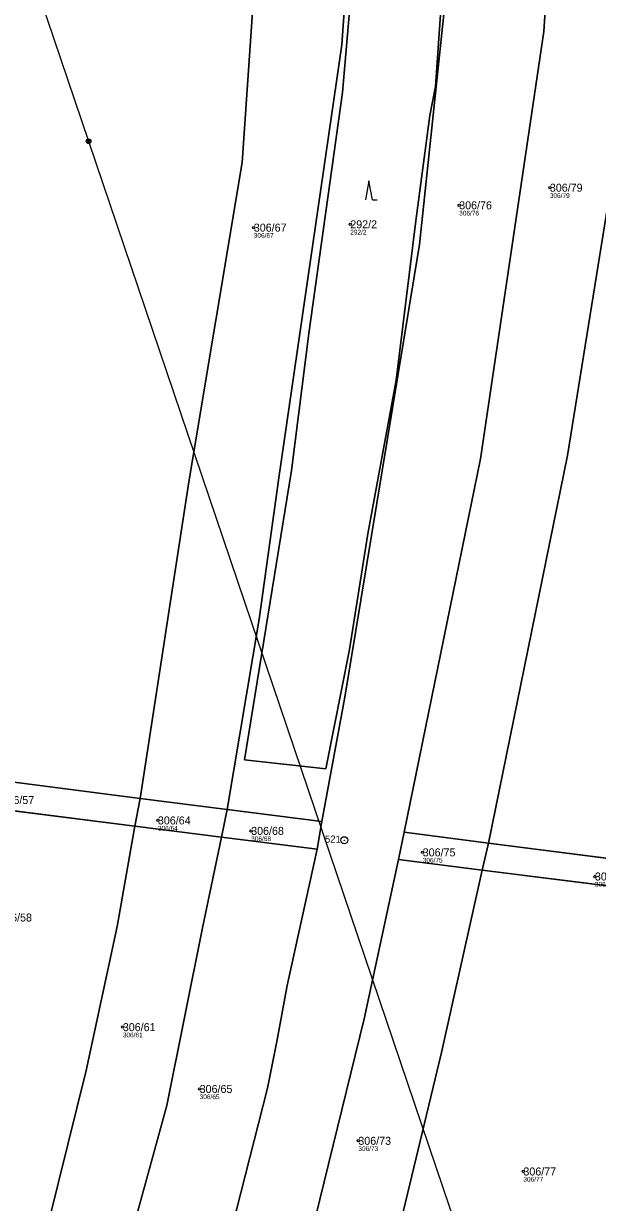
# Model space of a CAD drawing. Extents: x -732749 to -730903, y -1025757 to -1023435.
# Drawn here: x -732153.5 to -732031.6, y -1024046.3 to -1023795.9 of the extents above; entities that cross this region are included whole.
import ezdxf

# ---------------------------------------------------------------- set-up
doc = ezdxf.new("R2010")
doc.units = 0
for name, color, linetype in [('Definiční body', 7, 'Continuous'), ('Hranice parcel', 7, 'Continuous'), ('Parcelní čísla', 7, 'Continuous'), ('Polygon parcely', 7, 'Continuous'), ('Poz předměty', 7, 'Continuous'), ('Značky bodu BP', 7, 'Continuous'), ('Značky kultur', 7, 'Continuous')]:
    doc.layers.add(name, color=color, linetype=linetype)

msp = doc.modelspace()

# ---------------------------------------------------------------- linework, layer by layer
at = {"layer": 'Definiční body'}
for centre in [(-732041.74, -1023830.79), (-732061, -1023834.53), (-732084.13, -1023838.57), (-732104.62, -1023839.27), (-732124.99, -1023965.19), (-732105.18, -1023967.41), (-732068.74, -1023971.98), (-732032.17, -1023977.1), (-732132.44, -1024009.1), (-732116.12, -1024022.23), (-732082.42, -1024033.24), (-732047.36, -1024039.76)]:
    msp.add_circle(centre, 0.25, dxfattribs=at)
at = {"layer": 'Hranice parcel'}
for p, q in [((-732128.74, -1023960.5), (-732179.66, -1023953.96)), ((-732180.5, -1023959.99), (-732129.9, -1023966.39)), ((-732129.9, -1023966.39), (-732128.74, -1023960.5)), ((-732110.27, -1023962.87), (-732128.74, -1023960.5)), ((-732111.48, -1023968.72), (-732110.27, -1023962.87)), ((-732090.15, -1023965.45), (-732110.27, -1023962.87)), ((-732111.48, -1023968.72), (-732129.9, -1023966.39)), ((-732091.17, -1023971.29), (-732090.15, -1023965.45)), ((-732091.17, -1023971.29), (-732111.48, -1023968.72)), ((-732072.66, -1023967.7), (-732073.86, -1023973.48)), ((-732054.8, -1023969.99), (-732072.66, -1023967.7)), ((-732056.09, -1023975.73), (-732054.8, -1023969.99)), ((-732054.8, -1023969.99), (-732003.11, -1023976.63)), ((-732056.09, -1023975.73), (-732073.86, -1023973.48)), ((-732003.09, -1023982.44), (-732056.09, -1023975.73))]:
    msp.add_line(p, q, dxfattribs=at)
for points in [[(-732036.08, -1023589.28), (-732022.93, -1023663.95), (-732019.55, -1023730.55), (-732024.06, -1023791.81), (-732027.06, -1023819.97), (-732038.02, -1023887.66), (-732054.8, -1023969.99)], [(-732072.66, -1023967.7), (-732056.45, -1023888.41), (-732042.99, -1023797.62), (-732039.38, -1023741.93), (-732043.18, -1023668.74), (-732056.15, -1023593.74)], [(-732128.74, -1023960.5), (-732118.32, -1023892.87), (-732107.12, -1023825.41), (-732104.19, -1023783.08), (-732102.37, -1023712.48), (-732104.44, -1023690.34), (-732112.29, -1023646.68), (-732119.93, -1023609.35)], [(-732110.27, -1023962.87), (-732103.47, -1023922.44), (-732099.33, -1023892.42), (-732085.94, -1023800.46), (-732084.11, -1023774.04), (-732083.75, -1023721.22), (-732084.36, -1023701.11), (-732086.06, -1023667.51), (-732086.71, -1023664.35)], [(-732062.59, -1023702.22), (-732077.45, -1023704.23), (-732082.56, -1023729.6), (-732081.88, -1023757.53), (-732083.67, -1023785.88), (-732085.75, -1023810.56), (-732092.92, -1023861.75), (-732096.63, -1023890.89), (-732106.63, -1023952.3), (-732089.32, -1023954.25), (-732084.32, -1023928.9), (-732080.38, -1023904.28), (-732074.4, -1023871.65), (-732070.21, -1023837.84), (-732067.22, -1023815.43), (-732066.05, -1023809.26), (-732064.06, -1023780.67), (-732062.95, -1023756.61)], [(-732090.15, -1023965.45), (-732085.27, -1023938.99), (-732069.44, -1023842.88), (-732063.59, -1023787.85), (-732060.67, -1023744.81), (-732061.84, -1023718.91)], [(-732151.95, -1024065.77), (-732140.23, -1024018.31), (-732133.67, -1023987.73), (-732129.9, -1023966.39)], [(-732139.79, -1024086.53), (-732123.1, -1024025.74), (-732115.5, -1023988.01), (-732111.48, -1023968.72)], [(-732124.31, -1024110.73), (-732101.74, -1024022.07), (-732099.68, -1024011.8), (-732097.5, -1024000.25), (-732091.17, -1023971.29)], [(-732073.86, -1023973.48), (-732081.19, -1024007.32), (-732095.31, -1024065.03), (-732111.61, -1024129.23)], [(-732097.33, -1024149.54), (-732080.94, -1024081.88), (-732064.77, -1024014.51), (-732056.09, -1023975.73)]]:
    msp.add_lwpolyline(points, dxfattribs=at)
at = {"layer": 'Polygon parcely'}
for points in [[(-732042.6, -1023590.79), (-732056.15, -1023593.74), (-732043.18, -1023668.74), (-732039.38, -1023741.93), (-732042.99, -1023797.62), (-732056.45, -1023888.41), (-732072.66, -1023967.7), (-732054.8, -1023969.99), (-732038.02, -1023887.66), (-732027.06, -1023819.97), (-732024.06, -1023791.81), (-732019.55, -1023730.55), (-732022.93, -1023663.95), (-732036.08, -1023589.28)], [(-732084.11, -1023774.04), (-732083.75, -1023721.22), (-732084.36, -1023701.11), (-732086.06, -1023667.51), (-732086.71, -1023664.35), (-732099.14, -1023604.25), (-732105.34, -1023605.84), (-732107.54, -1023606.6), (-732119.93, -1023609.35), (-732112.29, -1023646.68), (-732104.44, -1023690.34), (-732102.37, -1023712.48), (-732104.19, -1023783.08), (-732107.12, -1023825.41), (-732118.32, -1023892.87), (-732128.74, -1023960.5), (-732110.27, -1023962.87), (-732103.47, -1023922.44), (-732099.33, -1023892.42), (-732085.94, -1023800.46)], [(-732084.32, -1023928.9), (-732080.38, -1023904.28), (-732074.4, -1023871.65), (-732070.21, -1023837.84), (-732067.22, -1023815.43), (-732066.05, -1023809.26), (-732064.06, -1023780.67), (-732062.95, -1023756.61), (-732061.84, -1023718.91), (-732062.59, -1023702.22), (-732077.45, -1023704.23), (-732082.56, -1023729.6), (-732081.88, -1023757.53), (-732083.67, -1023785.88), (-732085.75, -1023810.56), (-732092.92, -1023861.75), (-732096.63, -1023890.89), (-732106.63, -1023952.3), (-732089.32, -1023954.25)], [(-732179.66, -1023953.96), (-732180.5, -1023959.99), (-732129.9, -1023966.39), (-732128.74, -1023960.5)], [(-732140.23, -1024018.31), (-732133.67, -1023987.73), (-732129.9, -1023966.39), (-732180.5, -1023959.99), (-732182.72, -1023981.88), (-732168.36, -1024033.68), (-732166.14, -1024041.84), (-732151.95, -1024065.77)], [(-732111.48, -1023968.72), (-732110.27, -1023962.87), (-732128.74, -1023960.5), (-732129.9, -1023966.39)], [(-732090.15, -1023965.45), (-732110.27, -1023962.87), (-732111.48, -1023968.72), (-732091.17, -1023971.29)], [(-732139.79, -1024086.53), (-732123.1, -1024025.74), (-732115.5, -1023988.01), (-732111.48, -1023968.72), (-732129.9, -1023966.39), (-732133.67, -1023987.73), (-732140.23, -1024018.31), (-732151.95, -1024065.77)], [(-732091.17, -1023971.29), (-732111.48, -1023968.72), (-732115.5, -1023988.01), (-732123.1, -1024025.74), (-732139.79, -1024086.53), (-732124.31, -1024110.73), (-732101.74, -1024022.07), (-732099.68, -1024011.8), (-732097.5, -1024000.25)], [(-732072.66, -1023967.7), (-732073.86, -1023973.48), (-732056.09, -1023975.73), (-732054.8, -1023969.99)], [(-732003.11, -1023976.63), (-732054.8, -1023969.99), (-732056.09, -1023975.73), (-732003.09, -1023982.44), (-732002.86, -1023981.47), (-732001.89, -1023976.79)], [(-732095.31, -1024065.03), (-732111.61, -1024129.23), (-732097.33, -1024149.54), (-732080.94, -1024081.88), (-732064.77, -1024014.51), (-732056.09, -1023975.73), (-732073.86, -1023973.48), (-732081.19, -1024007.32)], [(-732056.09, -1023975.73), (-732064.77, -1024014.51), (-732080.94, -1024081.88), (-732097.33, -1024149.54), (-732089.08, -1024157.41), (-732078.69, -1024168.01), (-732061.81, -1024177.45), (-732053.95, -1024182.72), (-732042.4, -1024181.79), (-732033.04, -1024124.93), (-732026.75, -1024089.8), (-732013.67, -1024026.69), (-732003.09, -1023982.44)]]:
    msp.add_lwpolyline(points, close=True, dxfattribs=at)
for points in [[(-732063.59, -1023787.85), (-732069.44, -1023842.88), (-732085.27, -1023938.99), (-732090.15, -1023965.45), (-732091.17, -1023971.29), (-732097.5, -1024000.25), (-732099.68, -1024011.8), (-732101.74, -1024022.07), (-732124.31, -1024110.73), (-732111.61, -1024129.23), (-732095.31, -1024065.03), (-732081.19, -1024007.32), (-732073.86, -1023973.48), (-732072.66, -1023967.7), (-732056.45, -1023888.41), (-732042.99, -1023797.62), (-732039.38, -1023741.93)], [(-732084.11, -1023774.04), (-732085.94, -1023800.46), (-732099.33, -1023892.42), (-732103.47, -1023922.44), (-732110.27, -1023962.87), (-732090.15, -1023965.45), (-732085.27, -1023938.99), (-732069.44, -1023842.88), (-732063.59, -1023787.85)], [(-732064.06, -1023780.67), (-732066.05, -1023809.26), (-732067.22, -1023815.43), (-732070.21, -1023837.84), (-732074.4, -1023871.65), (-732080.38, -1023904.28), (-732084.32, -1023928.9), (-732089.32, -1023954.25), (-732106.63, -1023952.3), (-732096.63, -1023890.89), (-732092.92, -1023861.75), (-732085.75, -1023810.56), (-732083.67, -1023785.88)], [(-732156.48, -1023792.71), (-732157.8, -1023805.88), (-732159.04, -1023823.95), (-732159.91, -1023832.93), (-732161.71, -1023842.63), (-732163.76, -1023854.8), (-732165.07, -1023863.63), (-732166.25, -1023868.78), (-732169.72, -1023885.73), (-732171.34, -1023897.35), (-732173.14, -1023910.37), (-732174.69, -1023919.51), (-732175.63, -1023924.96), (-732177.24, -1023937.33), (-732178.42, -1023947.65), (-732179.66, -1023953.96), (-732128.74, -1023960.5), (-732118.32, -1023892.87), (-732107.12, -1023825.41), (-732104.19, -1023783.08)], [(-732027.06, -1023819.97), (-732038.02, -1023887.66), (-732054.8, -1023969.99), (-732003.11, -1023976.63)]]:
    msp.add_lwpolyline(points, dxfattribs=at)
at = {"layer": 'Poz předměty'}
for p, q in [((-732199.96, -1023642.8), (-732139.7, -1023820.93)), ((-732139.7, -1023820.93), (-731961.8, -1024346.4))]:
    msp.add_line(p, q, dxfattribs=at)
for radius in [0.5, 0.4, 0.3, 0.2, 0.1]:
    msp.add_circle((-732139.7, -1023820.93), radius, dxfattribs=at)
at = {"layer": 'Značky bodu BP'}
for radius in [0.75, 0.03]:
    msp.add_circle((-732085.4, -1023969.4), radius, dxfattribs=at)
at = {"layer": 'Značky kultur'}
for p, q in [((-732080.18, -1023829.35), (-732080.93, -1023833.35)), ((-732079.43, -1023833.35), (-732080.18, -1023829.35)), ((-732079.43, -1023833.35), (-732078.43, -1023833.35))]:
    msp.add_line(p, q, dxfattribs=at)

# ---------------------------------------------------------------- texts
at = {"layer": 'Definiční body'}
for s, p in [('306/79', (-732041.74, -1023832.95)), ('306/76', (-732061, -1023836.69)), ('306/67', (-732104.62, -1023841.43)), ('292/2', (-732084.13, -1023840.73)), ('306/64', (-732124.99, -1023967.35)), ('306/68', (-732105.18, -1023969.57)), ('306/75', (-732068.74, -1023974.14)), ('306/78', (-732032.17, -1023979.26)), ('306/61', (-732132.44, -1024011.26)), ('306/65', (-732116.12, -1024024.39)), ('306/73', (-732082.42, -1024035.4)), ('306/77', (-732047.36, -1024041.92))]:
    msp.add_text(s, height=1, dxfattribs=at).set_placement(p)
at = {"layer": 'Parcelní čísla'}
for s, p in [('306/79', (-732041.74, -1023831.64)), ('306/76', (-732061, -1023835.38)), ('306/67', (-732104.62, -1023840.12)), ('292/2', (-732084.13, -1023839.42)), ('306/57', (-732158.21, -1023961.71)), ('306/64', (-732124.99, -1023966.04)), ('306/68', (-732105.18, -1023968.26)), ('306/75', (-732068.74, -1023972.83)), ('306/78', (-732032.17, -1023977.95)), ('306/58', (-732158.69, -1023986.66)), ('306/61', (-732132.44, -1024009.95)), ('306/65', (-732116.12, -1024023.08)), ('306/73', (-732082.42, -1024034.09)), ('306/77', (-732047.36, -1024040.61))]:
    msp.add_text(s, height=1.7, dxfattribs=at).set_placement(p)
at = {"layer": 'Značky bodu BP'}
msp.add_text('521', height=1.5, dxfattribs=at).set_placement((-732089.5, -1023969.9))

doc.saveas('drawing.dxf')
